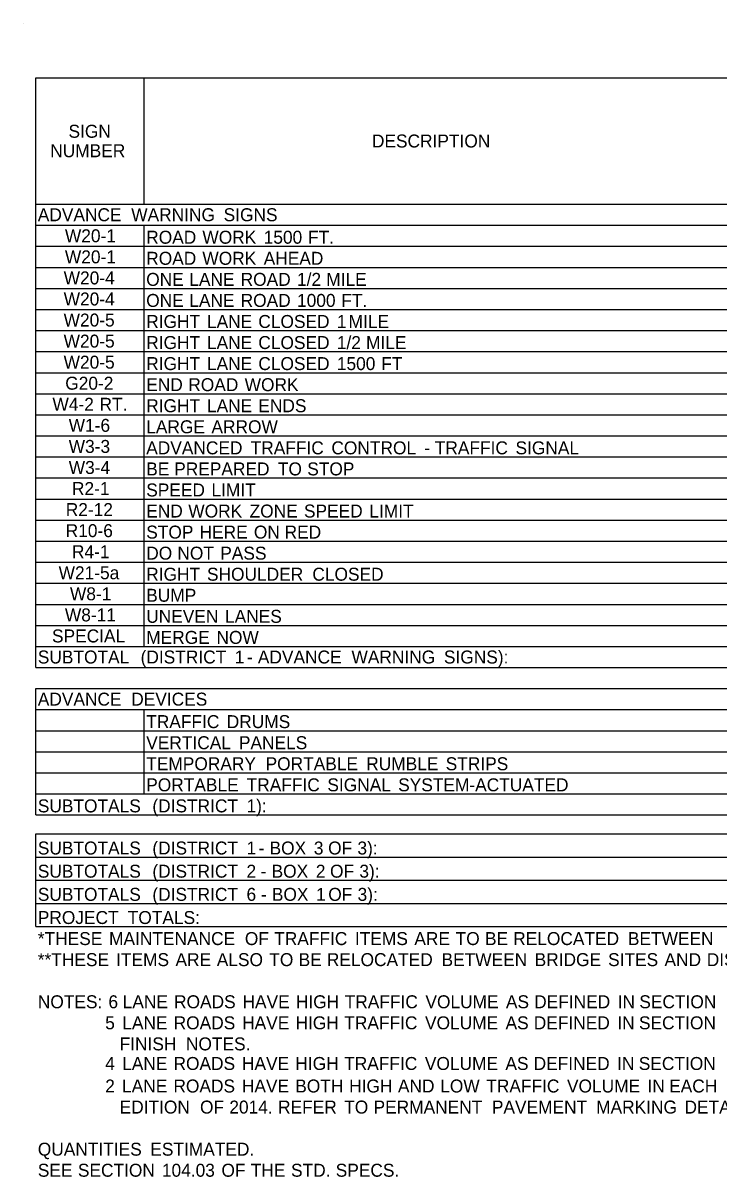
# Model space of a CAD drawing. Extents: x 542596 to 1930787, y -1948294 to 596640.
# Drawn here: x 548266 to 548589, y -1945683 to -1945148 of the extents above; entities that cross this region are included whole.
import ezdxf

# ---------------------------------------------------------------- set-up
doc = ezdxf.new("R2010")
doc.units = 0
doc.layers.add('Default', color=7, linetype='Continuous')

msp = doc.modelspace()

# ---------------------------------------------------------------- linework, layer by layer
at = {"layer": 'Default'}
for p, q in [((548266.23, -1945148.41), (548266.23, -1945148.41)), ((548272.08, -1945173.76), (549335.81, -1945173.76)), ((548272.08, -1945446.76), (548272.08, -1945173.76)), ((548272.08, -1945446.76), (548272.08, -1945173.76)), ((548322.3, -1945232.26), (548322.3, -1945173.76)), ((548272.08, -1945232.26), (549335.81, -1945232.26)), ((548272.08, -1945242.01), (549335.81, -1945242.01)), ((548322.3, -1945437.01), (548322.3, -1945242.01)), ((548322.3, -1945437.01), (548322.3, -1945242.01)), ((548272.08, -1945251.76), (549335.81, -1945251.76)), ((548272.08, -1945261.51), (549335.81, -1945261.51)), ((548272.08, -1945271.26), (549335.81, -1945271.26)), ((548272.08, -1945281.01), (549335.81, -1945281.01)), ((548272.08, -1945290.76), (549335.81, -1945290.76)), ((548272.08, -1945300.51), (549335.81, -1945300.51)), ((548272.08, -1945310.26), (549335.81, -1945310.26)), ((548272.08, -1945320.01), (549335.81, -1945320.01)), ((548272.08, -1945329.76), (549335.81, -1945329.76)), ((548272.08, -1945339.51), (549335.81, -1945339.51)), ((548272.08, -1945349.26), (549335.81, -1945349.26)), ((548272.08, -1945359.01), (549335.81, -1945359.01)), ((548272.08, -1945368.76), (549335.81, -1945368.76)), ((548272.08, -1945378.51), (549335.81, -1945378.51)), ((548272.08, -1945388.26), (549335.81, -1945388.26)), ((548272.08, -1945398.01), (549335.81, -1945398.01)), ((548272.08, -1945407.76), (549335.81, -1945407.76)), ((548272.08, -1945417.51), (549335.81, -1945417.51)), ((548272.08, -1945427.26), (549335.81, -1945427.26)), ((548272.08, -1945437.01), (548640.15, -1945437.01)), ((548272.08, -1945437.01), (549335.81, -1945437.01)), ((548272.08, -1945446.76), (549335.81, -1945446.76)), ((548272.08, -1945456.51), (549335.81, -1945456.51)), ((548272.08, -1945515.01), (548272.08, -1945456.51)), ((548272.08, -1945515.01), (548272.08, -1945456.51)), ((548272.08, -1945466.26), (549335.81, -1945466.26)), ((548322.3, -1945505.26), (548322.3, -1945466.26)), ((548322.3, -1945505.26), (548322.3, -1945466.26)), ((548272.08, -1945476.01), (549335.81, -1945476.01)), ((548272.08, -1945485.76), (549335.81, -1945485.76)), ((548272.08, -1945495.51), (549335.81, -1945495.51)), ((548272.08, -1945505.26), (549264.15, -1945505.26)), ((548272.08, -1945505.26), (548848.8, -1945505.26)), ((548272.08, -1945515.01), (549335.81, -1945515.01)), ((548272.08, -1945523.79), (549335.81, -1945523.79)), ((548272.08, -1945523.79), (549335.81, -1945523.79)), ((548272.08, -1945566.69), (548272.08, -1945523.79)), ((548272.08, -1945566.69), (548272.08, -1945523.79)), ((548272.08, -1945534.51), (549335.81, -1945534.51)), ((548272.08, -1945545.24), (549335.81, -1945545.24)), ((548272.08, -1945555.96), (549335.81, -1945555.96)), ((548272.08, -1945566.69), (549335.81, -1945566.69))]:
    msp.add_line(p, q, dxfattribs=at)

# ---------------------------------------------------------------- texts
for s, p in [('SIGN', (548287.28, -1945201.51)), ('DESCRIPTION', (548427.8, -1945206.01)), ('NUMBER', (548278.81, -1945210.51)), ('ADVANCE', (548273.06, -1945240.14)), (' WARNING', (548314.1, -1945240.14)), (' SIGNS', (548356.9, -1945240.14)), ('W20-1', (548285.62, -1945249.89)), ('ROAD', (548323.27, -1945250.56)), (' WORK', (548347.05, -1945250.56)), (' 1500', (548375.44, -1945250.56)), (' FT.', (548396, -1945250.56)), ('W20-1', (548285.62, -1945259.64)), ('ROAD', (548323.27, -1945260.31)), (' WORK', (548347.05, -1945260.31)), (' AHEAD', (548375.44, -1945260.31)), ('W20-4', (548285.05, -1945269.39)), ('ONE', (548323.27, -1945270.06)), (' LANE', (548340.99, -1945270.06)), (' ROAD', (548364.77, -1945270.06)), (' 1/2', (548390.88, -1945270.06)), (' MILE', (548404.41, -1945270.06)), ('W20-4', (548285.05, -1945279.14)), ('ONE', (548323.27, -1945279.81)), (' LANE', (548340.99, -1945279.81)), (' ROAD', (548364.77, -1945279.81)), (' 1000', (548390.88, -1945279.81)), (' FT.', (548411.44, -1945279.81)), ('W20-5', (548285.02, -1945288.89)), ('RIGHT', (548323.27, -1945289.56)), (' LANE', (548349.18, -1945289.56)), (' CLOSED', (548372.96, -1945289.56)), (' 1', (548409.32, -1945289.56)), (' MILE', (548414.77, -1945289.56)), ('W20-5', (548285.02, -1945298.64)), ('RIGHT', (548323.27, -1945299.31)), (' LANE', (548349.18, -1945299.31)), (' CLOSED', (548372.96, -1945299.31)), (' 1/2', (548409.32, -1945299.31)), (' MILE', (548422.85, -1945299.31)), ('W20-5', (548285.02, -1945308.39)), ('RIGHT', (548323.27, -1945309.06)), (' LANE', (548349.18, -1945309.06)), (' CLOSED', (548372.96, -1945309.06)), (' 1500', (548409.32, -1945309.06)), (' FT', (548429.89, -1945309.06)), ('G20-2', (548285.77, -1945318.14)), ('END', (548323.27, -1945318.81)), (' ROAD', (548340.53, -1945318.81)), (' WORK', (548366.63, -1945318.81)), ('W4-2', (548279.85, -1945327.89)), (' RT.', (548299.43, -1945327.89)), ('RIGHT', (548323.27, -1945328.56)), (' LANE', (548349.18, -1945328.56)), (' ENDS', (548372.96, -1945328.56)), ('W1-6', (548287.37, -1945337.64)), ('LARGE', (548323.27, -1945338.31)), (' ARROW', (548351.25, -1945338.31)), ('W3-3', (548287.37, -1945347.39)), ('ADVANCED', (548323.27, -1945348.06)), (' TRAFFIC', (548369.41, -1945348.06)), (' CONTROL', (548406.8, -1945348.06)), (' -', (548449.82, -1945348.06)), (' TRAFFIC', (548454.68, -1945348.06)), (' SIGNAL', (548492.07, -1945348.06)), ('W3-4', (548287.38, -1945357.14)), ('BE', (548323.27, -1945357.81)), (' PREPARED', (548334.01, -1945357.81)), (' TO', (548382.02, -1945357.81)), (' STOP', (548395.61, -1945357.81)), ('R2-1', (548288.88, -1945366.89)), ('SPEED', (548323.27, -1945367.56)), (' LIMIT', (548351.25, -1945367.56)), ('R2-12', (548286, -1945376.64)), ('END', (548323.27, -1945377.31)), (' WORK', (548340.53, -1945377.31)), (' ZONE', (548368.92, -1945377.31)), (' SPEED', (548394.09, -1945377.31)), (' LIMIT', (548424.39, -1945377.31)), ('R10-6', (548285.97, -1945386.39)), ('STOP', (548323.27, -1945387.06)), (' HERE', (548345.73, -1945387.06)), (' ON', (548370.91, -1945387.06)), (' RED', (548385.13, -1945387.06)), ('R4-1', (548288.88, -1945396.14)), ('DO', (548323.27, -1945396.81)), (' NOT', (548335.47, -1945396.81)), (' PASS', (548355.33, -1945396.81)), ('W21-5a', (548282.7, -1945405.89)), ('RIGHT', (548323.27, -1945406.56)), (' SHOULDER', (548349.18, -1945406.56)), (' CLOSED', (548397.98, -1945406.56)), ('W8-1', (548287.95, -1945415.64)), ('BUMP', (548323.27, -1945416.31)), ('W8-11', (548285.62, -1945425.39)), ('UNEVEN', (548323.27, -1945426.06)), (' LANES', (548357.53, -1945426.06)), ('SPECIAL', (548279.63, -1945435.14)), ('MERGE', (548323.27, -1945435.81)), (' NOW', (548353.57, -1945435.81)), ('SUBTOTAL', (548273.06, -1945444.89)), (' (DISTRICT', (548318.45, -1945444.89)), (' 1', (548362.05, -1945444.89)), (' -', (548367.68, -1945444.89)), (' ADVANCE', (548372.74, -1945444.89)), (' WARNING', (548416.11, -1945444.89)), (' SIGNS):', (548458.91, -1945444.89)), ('ADVANCE', (548273.06, -1945464.39)), (' DEVICES', (548314.1, -1945464.39)), ('TRAFFIC', (548323.27, -1945474.81)), (' DRUMS', (548358.33, -1945474.81)), ('VERTICAL', (548323.27, -1945484.56)), (' PANELS', (548363.97, -1945484.56)), ('TEMPORARY', (548323.27, -1945494.31)), (' PORTABLE', (548376.32, -1945494.31)), (' RUMBLE', (548422.93, -1945494.31)), (' STRIPS', (548459.74, -1945494.31)), ('PORTABLE', (548323.27, -1945504.06)), (' TRAFFIC', (548367.55, -1945504.06)), (' SIGNAL', (548404.94, -1945504.06)), (' SYSTEM-ACTUATED', (548437.72, -1945504.06)), ('SUBTOTALS', (548273.06, -1945513.81)), (' (DISTRICT', (548323.89, -1945513.81)), (' 1):', (548367.49, -1945513.81)), ('SUBTOTALS', (548273.06, -1945533.31)), (' (DISTRICT', (548323.89, -1945533.31)), (' 1', (548367.49, -1945533.31)), (' BOX', (548378.17, -1945533.31)), (' 3', (548398.66, -1945533.31)), (' OF', (548405.29, -1945533.31)), (' 3):', (548418.87, -1945533.31)), (' -', (548373.12, -1945533.31)), ('SUBTOTALS', (548273.06, -1945544.04)), (' (DISTRICT', (548323.89, -1945544.04)), (' 2', (548367.49, -1945544.04)), (' BOX', (548379.11, -1945544.04)), (' 2', (548399.6, -1945544.04)), (' OF', (548406.17, -1945544.04)), (' 3):', (548419.75, -1945544.04)), (' -', (548374.05, -1945544.04)), ('SUBTOTALS', (548273.06, -1945554.76)), (' (DISTRICT', (548323.89, -1945554.76)), (' 6', (548367.49, -1945554.76)), (' BOX', (548379.23, -1945554.76)), (' 1', (548399.72, -1945554.76)), (' OF', (548405.35, -1945554.76)), (' 3):', (548418.93, -1945554.76)), (' -', (548374.18, -1945554.76)), ('PROJECT', (548273.06, -1945565.49)), (' TOTALS:', (548312.48, -1945565.49)), ('*THESE', (548273.06, -1945575.24)), (' MAINTENANCE', (548303.83, -1945575.24)), (' OF', (548366.73, -1945575.24)), (' TRAFFIC', (548380.32, -1945575.24)), (' ITEMS', (548417.71, -1945575.24)), (' ARE', (548445.22, -1945575.24)), (' TO', (548464.34, -1945575.24)), (' BE', (548477.93, -1945575.24)), (' RELOCATED', (548491, -1945575.24)), (' BETWEEN', (548544.12, -1945575.24)), ('**THESE', (548273.06, -1945584.99)), (' ITEMS', (548307.09, -1945584.99)), (' ARE', (548334.6, -1945584.99)), (' ALSO', (548353.72, -1945584.99)), (' TO', (548378.04, -1945584.99)), (' BE', (548391.63, -1945584.99)), (' RELOCATED', (548404.7, -1945584.99)), (' BETWEEN', (548457.82, -1945584.99)), (' BRIDGE', (548500.93, -1945584.99)), (' SITES', (548534.95, -1945584.99)), (' AND', (548561.07, -1945584.99)), (' DISTRICTS', (548580.65, -1945584.99)), ('NOTES:', (548273.06, -1945604.49)), (' 6', (548303.54, -1945604.49)), (' LANE', (548310.15, -1945604.49)), (' ROADS', (548333.93, -1945604.49)), (' HAVE', (548365.63, -1945604.49)), (' HIGH', (548390.35, -1945604.49)), (' TRAFFIC', (548412.96, -1945604.49)), (' VOLUME', (548450.35, -1945604.49)), (' AS', (548487.63, -1945604.49)), (' DEFINED', (548500.71, -1945604.49)), (' IN', (548539.39, -1945604.49)), (' SECTION', (548549.41, -1945604.49)), ('              5', (548273.06, -1945614.24)), (' LANE', (548309.97, -1945614.24)), (' ROADS', (548333.75, -1945614.24)), (' HAVE', (548365.46, -1945614.24)), (' HIGH', (548390.17, -1945614.24)), (' TRAFFIC', (548412.78, -1945614.24)), (' VOLUME', (548450.17, -1945614.24)), (' AS', (548487.46, -1945614.24)), (' DEFINED', (548500.53, -1945614.24)), (' IN', (548539.21, -1945614.24)), (' SECTION', (548549.24, -1945614.24)), ('                 FINISH', (548273.06, -1945623.99)), (' NOTES.', (548339.43, -1945623.99)), ('              4', (548273.06, -1945633.06)), (' LANE', (548309.9, -1945633.06)), (' ROADS', (548333.68, -1945633.06)), (' HAVE', (548365.39, -1945633.06)), (' HIGH', (548390.1, -1945633.06)), (' TRAFFIC', (548412.71, -1945633.06)), (' VOLUME', (548450.1, -1945633.06)), (' AS', (548487.39, -1945633.06)), (' DEFINED', (548500.46, -1945633.06)), (' IN', (548539.14, -1945633.06)), (' SECTION', (548549.16, -1945633.06)), ('              2', (548273.06, -1945643.49)), (' LANE', (548309.86, -1945643.49)), (' ROADS', (548333.64, -1945643.49)), (' HAVE', (548365.35, -1945643.49)), (' BOTH', (548390.06, -1945643.49)), (' HIGH', (548415.01, -1945643.49)), (' AND', (548437.62, -1945643.49)), (' LOW', (548457.2, -1945643.49)), (' TRAFFIC', (548478.52, -1945643.49)), (' VOLUME', (548515.91, -1945643.49)), (' IN', (548553.2, -1945643.49)), (' EACH', (548563.22, -1945643.49)), ('                 EDITION', (548273.06, -1945653.24)), (' OF', (548345.95, -1945653.24)), (' 2014.', (548359.53, -1945653.24)), (' REFER', (548382.1, -1945653.24)), (' TO', (548412.73, -1945653.24)), (' PERMANENT', (548426.32, -1945653.24)), (' PAVEMENT', (548481.12, -1945653.24)), (' MARKING', (548529.41, -1945653.24)), (' DETAILS', (548570.34, -1945653.24)), ('QUANTITIES', (548273.06, -1945672.74)), (' ESTIMATED.', (548322.93, -1945672.74)), ('SEE', (548273.06, -1945682.49)), (' SECTION', (548289.39, -1945682.49)), (' 104.03', (548328.3, -1945682.49)), (' OF', (548355.87, -1945682.49)), (' THE', (548369.46, -1945682.49)), (' STD.', (548388.11, -1945682.49)), (' SPECS.', (548408.8, -1945682.49))]:
    msp.add_text(s, height=6, dxfattribs=at).set_placement(p)

doc.saveas('drawing.dxf')
